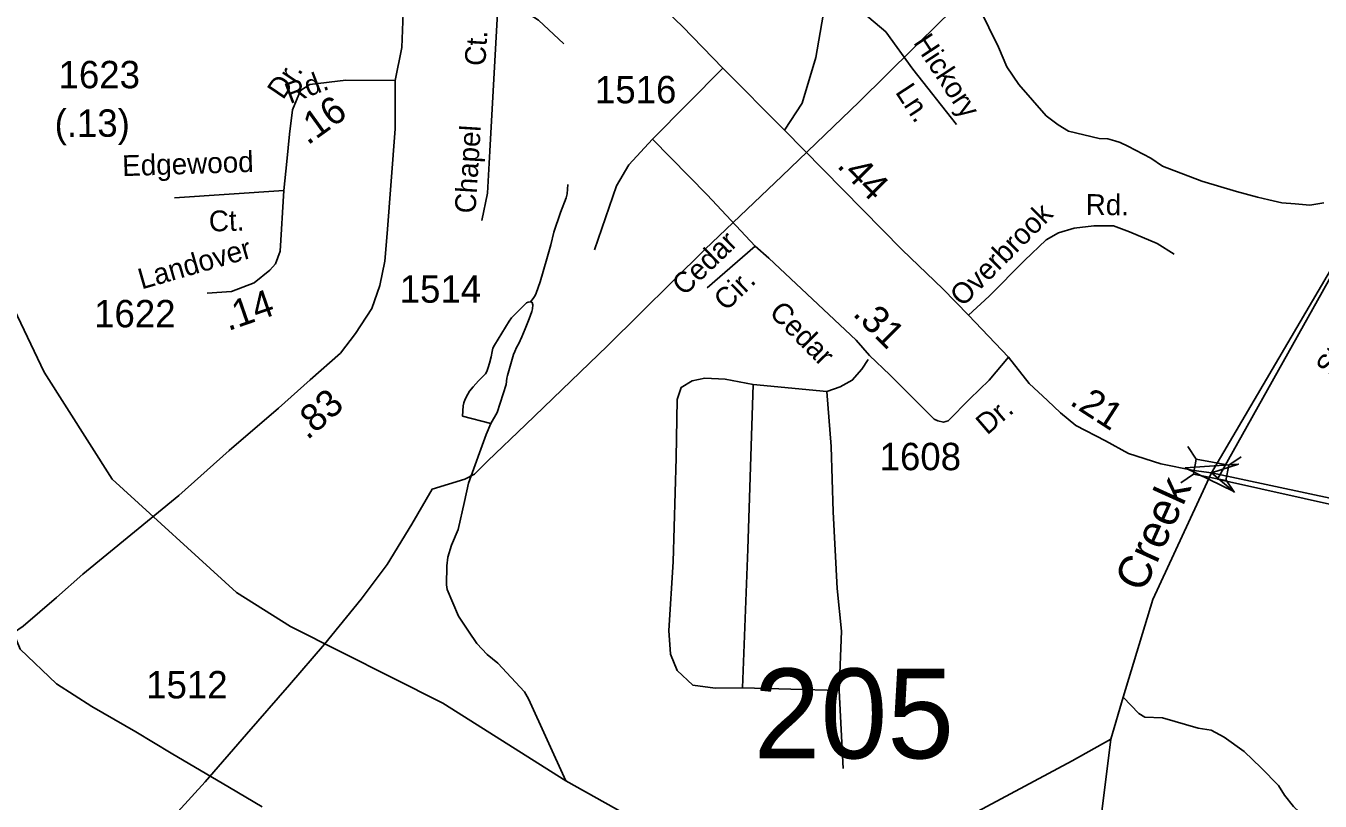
# Model space of a CAD drawing. Extents: x 1473865 to 1648260, y 639067 to 773536.
# Drawn here: x 1534546 to 1540456, y 689946 to 693485 of the extents above; entities that cross this region are included whole.
import ezdxf

# ---------------------------------------------------------------- set-up
doc = ezdxf.new("R2010")
doc.units = 0
for name, color, linetype in [('Exist Boundary Political City Limit New', 7, 'Continuous'), ('Exist Hydrographic Creek Single Shore', 7, 'Continuous'), ('Exist Hydrographic Creek Single Shore Label', 7, 'Continuous'), ('Exist Hydrographic Misc Water Feature', 7, 'Continuous'), ('Exist Road Non-System Type 51', 7, 'Continuous'), ('Exist Road Non-System Type 51 Label', 7, 'Continuous'), ('Exist Road Secondary Mileage Hundredths English Label', 7, 'Continuous'), ('Exist Road Secondary Structure Standard Bridge Attributed CELL', 7, 'Continuous'), ('Exist Road Secondary Structure Standard Bridge CELL', 7, 'Continuous'), ('Exist Road Secondary Structure Standard Bridge Number Label', 7, 'Continuous'), ('Exist Road Secondary Type 51 Attributed', 7, 'Continuous'), ('Exist Road Secondary Type 51 Label', 7, 'Continuous'), ('Exist Road Secondary Type 51 Number Label', 7, 'Continuous'), ('Exist Utilities Electrical Transmission Line', 7, 'Continuous'), ('Map Preparation Boundary City Limit Buffer Line', 7, 'Continuous')]:
    doc.layers.add(name, color=color, linetype=linetype)

msp = doc.modelspace()

# ---------------------------------------------------------------- linework, layer by layer
at = {"layer": 'Exist Boundary Political City Limit New'}
msp.add_lwpolyline([(1540722.9, 692728.8), (1539987.1, 691415.6), (1541187.6, 691147.4)], dxfattribs=at)
at = {"layer": 'Exist Hydrographic Creek Single Shore'}
for points in [[(1537498.9, 689765.2), (1537012.2, 690038.3), (1536449.8, 690392.6), (1535754.4, 690742.8), (1535507.4, 690898.7), (1534940.4, 691415.6), (1534630.4, 691904.5), (1534477.4, 692222.7), (1534310.4, 692718.4), (1534277.4, 692768.3), (1534050.4, 693705.1), (1534085.5, 693806.1), (1534204.4, 693944.9), (1534247.5, 694052.3), (1534276.5, 694301.2), (1534508.5, 694723.3), (1534561.5, 694915.9), (1534578.4, 695440.8), (1534764.5, 695653.6), (1534808.5, 695754.5), (1534853.6, 695939.4)], [(1539501.1, 690228.5), (1539556.1, 690420.3), (1539691.5, 690866.8), (1539959.5, 691444.3), (1540601.5, 692535.6), (1540858.5, 692940.7), (1540959.5, 693030.6), (1541286.5, 693165.2), (1541506.5, 693338), (1541673.5, 693393.7)], [(1538210.5, 687297.6), (1538307.2, 687320.4), (1538429.4, 687431.3), (1538492, 687482.5), (1538699.5, 687567.9), (1538872.9, 687678.9), (1538992.3, 687804.1), (1539134.5, 688314.4), (1539377.6, 689237.9), (1539501.1, 690228.5)], [(1539501.1, 690228.5), (1539324.5, 690129.1), (1538825.5, 689863.4)]]:
    msp.add_lwpolyline(points, dxfattribs=at)
at = {"layer": 'Exist Hydrographic Misc Water Feature'}
for points in [[(1540473.7, 692677.2), (1540409.5, 692666.5), (1540341.5, 692671.8), (1540281.6, 692677.1), (1540221.9, 692690.3), (1540170.1, 692703.3), (1540074.6, 692729.2), (1539915.5, 692776.5), (1539736.7, 692844), (1539683.5, 692881.1), (1539578.5, 692935.2), (1539542.8, 692951.9), (1539518.9, 692960.4), (1539487.2, 692969.1), (1539447.2, 692969.9), (1539307.7, 693004.7), (1539260.1, 693032.5), (1539205.1, 693074.7), (1539079.8, 693217.2), (1539025.4, 693298.3), (1538987.1, 693387), (1538898.7, 693566.7)], [(1536850.7, 692224.9), (1536863.2, 692240.2), (1536871.5, 692253.2), (1536876.3, 692264.7), (1536886, 692289.7), (1536894.7, 692316.8), (1536925.1, 692420.7), (1536942.7, 692484.5), (1536957, 692542.3), (1536987.8, 692632.1), (1537012.9, 692699.7), (1537017.3, 692717.8), (1537021.3, 692760.1)], [(1536668.9, 691669.9), (1536540, 691703.7), (1536543, 691750.1), (1536545.8, 691763.2), (1536552.8, 691780.7), (1536563.8, 691803.7), (1536572.2, 691816.7), (1536588.3, 691837), (1536613.2, 691864.8), (1536634.3, 691885.5), (1536645.1, 691895.9), (1536650.5, 691906.9), (1536656.9, 691925.4), (1536663.9, 691945.5), (1536670.6, 691974.1), (1536675.1, 691998.3), (1536679, 692012.9), (1536686.4, 692026.8), (1536753.3, 692136), (1536763.8, 692151.5), (1536779.2, 692167.3), (1536832.5, 692220.2), (1536839.1, 692223.5), (1536850.7, 692224.9)], [(1536850.7, 692224.9), (1536857.8, 692222.2), (1536860.5, 692212), (1536859.2, 692192.8), (1536855.9, 692180.7), (1536844, 692147.7), (1536826.4, 692101.6), (1536811.5, 692065.5), (1536796.7, 692034.5), (1536786.7, 692016.1), (1536778.2, 691998.5), (1536772.9, 691984.5), (1536748.4, 691899.2), (1536745.6, 691889.1), (1536742.8, 691876.6), (1536739.7, 691846.9), (1536698, 691719.9), (1536668.9, 691669.9)], [(1537012.2, 690038.3), (1536840.8, 690412), (1536823.4, 690444.4), (1536701.9, 690574.7), (1536652.7, 690615.7), (1536605.7, 690664.6), (1536566.8, 690721.4), (1536522.1, 690790.3), (1536470.4, 690911.3), (1536466.8, 690933.3), (1536468.5, 691019.3), (1536473.3, 691059.1), (1536490.4, 691114.8), (1536519.7, 691186.1), (1536549.1, 691312.9), (1536567.9, 691397.1), (1536648.2, 691619.3), (1536668.9, 691669.9)], [(1539556.1, 690420.3), (1539628.1, 690345.4), (1539655.8, 690328.9), (1539735.8, 690325.3), (1539898.9, 690278), (1539958.7, 690268.8), (1540018.1, 690237.6), (1540108.9, 690171.7), (1540187.4, 690098.2), (1540265.8, 690016.6), (1540292.8, 689972.4), (1540334.7, 689921.3), (1540391, 689868.2), (1540532.8, 689751.3), (1540588, 689708.3), (1540746.4, 689625.1), (1540791.9, 689594.3), (1540861.1, 689558.8), (1540904.8, 689541.9), (1541103.5, 689473.9), (1541159.2, 689456.8), (1541230.8, 689437.3)]]:
    msp.add_lwpolyline(points, dxfattribs=at)
at = {"layer": 'Exist Road Non-System Type 51'}
for points in [[(1536700.8, 693571), (1536664.6, 692913.1), (1536653.8, 692721), (1536628.6, 692596.4)], [(1536700.8, 693571), (1536755, 693587.3), (1536810.9, 693560.2), (1536886.7, 693511.4), (1537002.1, 693403.1)], [(1538011, 693008.3), (1538090.8, 693131.3), (1538153.9, 693340.8), (1538200.4, 693613.6)], [(1538200.4, 693613.6), (1538290.2, 693593.6), (1538366.6, 693547), (1538473, 693457.2), (1538595.9, 693287.6), (1538795.3, 693034.9)], [(1537728.1, 693292.3), (1537408.1, 692968.1)], [(1537408.1, 692968.1), (1537299.7, 692851), (1537242.6, 692753.9), (1537142.7, 692462.6)], [(1537408.1, 692968.1), (1537656.4, 692713.9), (1537876.2, 692479.7)], [(1539789, 692442.5), (1539711.6, 692491.5), (1539586, 692544.6), (1539512.3, 692571.5), (1539422.3, 692572.4), (1539332.2, 692561.4), (1539261.9, 692540), (1539205.7, 692508.7), (1539106.7, 692413.6), (1538945.1, 692251.2), (1538851.1, 692164.1)], [(1537876.2, 692479.7), (1537656.4, 692288.4)], [(1538391.6, 691961.8), (1538363.8, 691917.7), (1538319.8, 691866.8), (1538264.3, 691836.7), (1538204.2, 691815.9)], [(1537866.6, 691848.3), (1537739.4, 691871.4), (1537646.9, 691876), (1537589.1, 691864.5), (1537538.2, 691834.4), (1537519.7, 691778.8), (1537515.1, 691512.7), (1537501.3, 691037.4), (1537482.8, 690725), (1537489.7, 690616.2), (1537519.8, 690542.2), (1537591.5, 690475), (1537693.2, 690461.2), (1537818.1, 690463.5)], [(1537866.6, 691848.3), (1537843.4, 691096.6), (1537818.1, 690463.5)], [(1538204.2, 691815.9), (1537866.6, 691848.3)], [(1538204.2, 691815.9), (1538222.6, 691564.1), (1538231.8, 691265.6), (1538250.3, 690916.1), (1538271, 690721.2), (1538259.8, 690450)], [(1537818.1, 690463.5), (1538259.8, 690450)], [(1538259.8, 690450), (1538277.9, 690094)]]:
    msp.add_lwpolyline(points, dxfattribs=at)
at = {"layer": 'Exist Road Secondary Structure Standard Bridge Attributed CELL'}
msp.add_lwpolyline([(1540058.8, 691360.5), (1539839.8, 691467.7), (1540083.1, 691484.3), (1539959.5, 691444.3)], close=True, dxfattribs=at)
at = {"layer": 'Exist Road Secondary Structure Standard Bridge CELL'}
for p, q in [((1539851.8, 691563.9), (1539890.7, 691506.9)), ((1540039.2, 691478.7), (1540096.1, 691517.6)), ((1539820.7, 691398.6), (1539877.7, 691437.5)), ((1540026.4, 691410.8), (1540065.3, 691353.9))]:
    msp.add_line(p, q, dxfattribs=at)
msp.add_lwpolyline([(1539890.7, 691506.9), (1540039.2, 691479), (1540026.2, 691409.6), (1539877.7, 691437.5)], close=True, dxfattribs=at)
at = {"layer": 'Exist Road Secondary Type 51 Attributed'}
msp.add_line((1535724.5, 692733.5), (1535224.9, 692700.4), dxfattribs=at)
for points in [[(1536223.8, 694016.8), (1536248.7, 693941.5), (1536259.8, 693889.3), (1536271, 693797.2), (1536276.6, 693624.9), (1536268.3, 693544.2), (1536262.7, 693385.8), (1536232.6, 693234.8)], [(1537405.3, 693615.7), (1537545.1, 693481.3), (1537728.1, 693292.3), (1538011, 693008.3), (1538187.2, 692828.8), (1538547.6, 692462.9), (1538732.9, 692284.1), (1538851.1, 692164.1), (1539033.5, 691972.6)], [(1536232.6, 693234.8), (1536232.6, 693015.2), (1536196.5, 692537.1), (1536185.3, 692410.5), (1536163.1, 692299.3), (1536125.5, 692195), (1536051.4, 692080.1), (1535982.6, 691990.8), (1535843.7, 691868.4), (1535700.1, 691739.1), (1535474.2, 691545.6), (1535245.1, 691341.2), (1534806.1, 690981.2), (1534686.6, 690875.5), (1534534.3, 690744.8), (1534489.4, 690714.3)], [(1536232.6, 693234.8), (1536006.6, 693236.2), (1535843.1, 693217.8), (1535800.9, 693190.2), (1535763.2, 693101.4), (1535749.3, 692990.2), (1535738.2, 692865.1), (1535724.5, 692733.5)], [(1535724.5, 692733.5), (1535707.7, 692456.5), (1535685.4, 692398.1), (1535660.4, 692370.3), (1535588.2, 692312), (1535485.4, 692272.4), (1535374.4, 692264.7)], [(1539033.5, 691972.6), (1538945.4, 691866.7), (1538857.2, 691781.4), (1538757.3, 691681.4), (1538736.7, 691675.5), (1538710.2, 691681.4), (1538693.7, 691689.4), (1538491.6, 691891.6), (1538398.5, 691980.2), (1538337.1, 692049.4), (1537938, 692424.8), (1537876.2, 692479.7)], [(1539033.5, 691972.6), (1539128, 691851.5), (1539210.9, 691774.2), (1539270.1, 691718.8), (1539340.5, 691660), (1539476.4, 691590.2), (1539581.1, 691532.3), (1539729.2, 691485.4), (1539878.8, 691454.5), (1539959.5, 691444.3)], [(1539959.5, 691444.3), (1541513.5, 691112.1), (1541695.6, 691068.7), (1541910.7, 691005.3), (1542131.3, 690939.6), (1542352.4, 690878.1), (1542555.6, 690848), (1542727.3, 690827.3), (1542868.6, 690823.4), (1542983.9, 690823.4), (1543161.1, 690837.5), (1543293.2, 690845.9), (1543563.2, 690862.8), (1543878.2, 690893.8), (1544169.7, 690938.5), (1544432.7, 690942.8)], [(1534489.4, 690714.3), (1534520, 690639.3), (1534686.6, 690480.8), (1534847.7, 690378), (1535047.7, 690261.2), (1535209.7, 690165.2), (1535476, 690008), (1535625.4, 689920)]]:
    msp.add_lwpolyline(points, dxfattribs=at)
at = {"layer": 'Exist Utilities Electrical Transmission Line'}
msp.add_lwpolyline([(1540708, 695288.4), (1540348.4, 694964.3), (1539954.5, 694612.8), (1539568.8, 694279.3), (1539253.8, 693990.7), (1538975.7, 693745.2), (1538725.6, 693507.5), (1538351.3, 693137.7), (1537997.5, 692799.4), (1537647.8, 692465.3), (1537202.3, 692024.7), (1536828.2, 691663), (1536655.4, 691499.8), (1536594.3, 691438.8), (1536549.9, 691415.5), (1536401.1, 691370.1), (1536308.4, 691209.7), (1536195.2, 691025.5), (1536076.5, 690867.4), (1535909.1, 690662.3), (1535749.9, 690476.8), (1535554.1, 690252), (1535364.3, 690033.2), (1535240.1, 689897.2)], dxfattribs=at)
at = {"layer": 'Map Preparation Boundary City Limit Buffer Line'}
msp.add_lwpolyline([(1540722.9, 692728.8), (1539987.1, 691415.6), (1541187.6, 691147.4)], dxfattribs=at)

# ---------------------------------------------------------------- texts
at = {"layer": 'Exist Hydrographic Creek Single Shore Label'}
msp.add_text('Creek', height=150, rotation=65.58567, dxfattribs=at).set_placement((1539649.4, 690893.2))
at = {"layer": 'Exist Road Non-System Type 51 Label'}
for s, rotation, p in [('Ct.', 86.38277, (1536643.8, 693299.6)), ('Hickory', 303.28615, (1538596, 693409)), ('Ln.', 303.28615, (1538513.3, 693182.4)), ('Chapel', 86.38277, (1536598.8, 692626.5)), ('Rd.', 359.48009, (1539385.2, 692621.9)), ('Overbrook', 45.15201, (1538823.7, 692198.9)), ('Cedar', 43.90072, (1537552.4, 692248.4)), ('Stoneybrook', 58.02789, (1540510.7, 691879.1)), ('Cir.', 43.90072, (1537743.2, 692178.7))]:
    msp.add_text(s, height=95, rotation=rotation, dxfattribs=at).set_placement(p)
at = {"layer": 'Exist Road Secondary Mileage Hundredths English Label'}
for s, rotation, p in [('.16', 35.80026, (1535832.9, 692937.5)), ('(.13)', 0.23051, (1534677.6, 692977.5)), ('.44', 314.56827, (1538245, 692843.4)), ('.14', 19.10441, (1535469.9, 692091.2)), ('.31', 314.97675, (1538317.7, 692166.4)), ('.83', 41.50707, (1535831.9, 691591.2)), ('.21', 327.24239, (1539307.4, 691759))]:
    msp.add_text(s, height=125, rotation=rotation, dxfattribs=at).set_placement(p)
at = {"layer": 'Exist Road Secondary Structure Standard Bridge Number Label'}
msp.add_text('205', height=410.1, dxfattribs=at).set_placement((1537869.6, 690140.8))
at = {"layer": 'Exist Road Secondary Type 51 Label'}
for s, rotation, p in [('Dr.', 55.96759, (1535720.5, 693143.8)), ('Rd.', 20.95092, (1535751.9, 693127.3)), ('Edgewood', 1.90153, (1534987.5, 692798.6)), ('Ct.', 1.90153, (1535383.2, 692545.4)), ('Landover', 16.08591, (1535074.8, 692281.1)), ('Cedar', 314.92914, (1537935.6, 692170.8)), ('Dr.', 40.73332, (1538935.4, 691613.8))]:
    msp.add_text(s, height=95, rotation=rotation, dxfattribs=at).set_placement(p)
at = {"layer": 'Exist Road Secondary Type 51 Number Label'}
for s, p in [('1623', (1534695.4, 693200)), ('1516', (1537144.7, 693131.3)), ('1514', (1536253.1, 692221)), ('1622', (1534857.8, 692108.6)), ('1608', (1538444.5, 691456.3)), ('1512', (1535095.5, 690414.5))]:
    msp.add_text(s, height=125, dxfattribs=at).set_placement(p)

doc.saveas('drawing.dxf')
